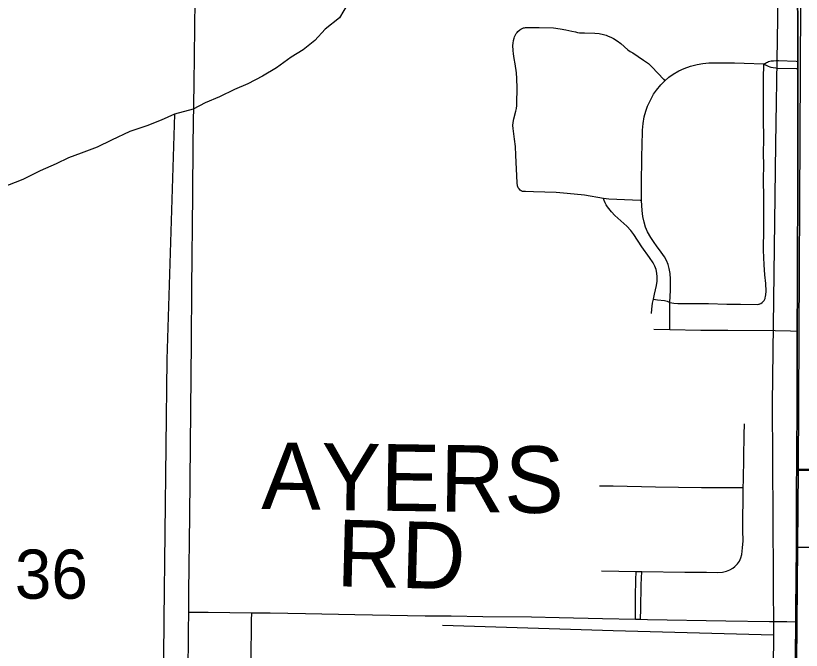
# Model space of a CAD drawing. Extents: x 0 to 34, y 0 to 22.
# Drawn here: x 7.896 to 8.565, y 18.272 to 18.813 of the extents above; entities that cross this region are included whole.
import ezdxf

# ---------------------------------------------------------------- set-up
doc = ezdxf.new("R2010")
doc.units = 0
for name, color, linetype in [('GM_X_Corporation', 7, 'Continuous'), ('GM_X_County_Road', 7, 'Continuous'), ('GM_X_Minor_River', 7, 'Continuous'), ('GM_X_Section_Text', 7, 'Continuous'), ('GM_X_Township_Road', 7, 'Continuous'), ('GM_X_Township_Road_Text', 7, 'Continuous')]:
    doc.layers.add(name, color=color, linetype=linetype)

msp = doc.modelspace()

# ---------------------------------------------------------------- linework, layer by layer
at = {"layer": 'GM_X_Corporation'}
for points in [[(8.9, 18.42344), (8.9, 19.44053), (8.56962, 19.44742), (8.56457, 18.82324), (8.56257, 18.42645)], [(7.52848, 18.83427), (8.56457, 18.82324), (8.56257, 18.42645), (8.55788, 17.86518), (7.51498, 17.8763)], [(8.9, 17.41639), (8.9, 18.42344), (8.56257, 18.42645), (8.55788, 17.86518), (8.55531, 17.77577), (8.50493, 17.42275)]]:
    msp.add_lwpolyline(points, close=True, dxfattribs=at)
for points in [[(8.56206, 18.83463), (8.56221, 18.79981), (8.56224, 18.77437), (8.56225, 18.7682), (8.56229, 18.73825), (8.56221, 18.68477), (8.56191, 18.58217), (8.56179, 18.54468), (8.56173, 18.52433), (8.56163, 18.48454), (8.56135, 18.43419), (8.56132, 18.42617), (8.56127, 18.41491), (8.56115, 18.36143), (8.56114, 18.36061), (8.56058, 18.30672), (8.56052, 18.29711), (8.56015, 18.23686)], [(8.56015, 18.23686), (8.56052, 18.29711), (8.56058, 18.30672), (8.56114, 18.36061), (8.56115, 18.36143), (8.56127, 18.41491), (8.56132, 18.42617), (8.56135, 18.43419), (8.56163, 18.48454), (8.56173, 18.52433), (8.56179, 18.54468), (8.56191, 18.58217), (8.56221, 18.68477), (8.56229, 18.73825), (8.56225, 18.7682), (8.56224, 18.77437), (8.56221, 18.79981), (8.56206, 18.83463)]]:
    msp.add_lwpolyline(points, dxfattribs=at)
at = {"layer": 'GM_X_County_Road'}
msp.add_line((8.56037, 18.2363), (8.56075, 18.29655), dxfattribs=at)
for points in [[(8.56248, 18.76765), (8.56247, 18.77381), (8.56244, 18.79925), (8.56228, 18.83407), (8.56174, 18.88072), (8.56186, 18.92237), (8.56166, 18.95472), (8.56187, 18.98456), (8.56193, 19.02064), (8.56195, 19.04425), (8.56203, 19.08291), (8.56208, 19.11277)], [(8.04319, 18.30453), (8.04338, 18.32156), (8.04407, 18.38685), (8.04485, 18.47638), (8.0455, 18.53483), (8.04584, 18.58086), (8.04665, 18.66043), (8.04704, 18.70333), (8.04789, 18.75462), (8.04863, 18.82659), (8.04849, 18.86078), (8.0482, 18.93739), (8.04843, 19.00255), (8.04869, 19.0766)], [(8.56202, 18.54413), (8.56213, 18.58161), (8.56244, 18.68421), (8.56252, 18.7377), (8.56248, 18.76765)], [(8.56154, 18.42562), (8.56157, 18.43363), (8.56186, 18.48398), (8.56196, 18.52378), (8.56202, 18.54413)], [(8.56137, 18.36006), (8.56138, 18.36088), (8.5615, 18.41435), (8.56154, 18.42562)], [(8.56075, 18.29655), (8.5608, 18.30617), (8.56137, 18.36006)], [(8.0419, 18.15097), (8.04211, 18.19851), (8.04274, 18.25005), (8.04302, 18.28863), (8.04319, 18.30453)]]:
    msp.add_lwpolyline(points, dxfattribs=at)
at = {"layer": 'GM_X_Minor_River'}
for points in [[(8.55117, 19.1356), (8.54966, 19.01986), (8.54597, 18.88176), (8.54328, 18.70341), (8.54041, 18.48254), (8.54164, 18.28513), (8.53923, 18.06955), (8.53751, 17.90633)], [(8.17916, 18.82335), (8.17182, 18.81092), (8.1596, 18.80121), (8.15079, 18.79145), (8.14086, 18.7836), (8.13058, 18.77728), (8.118, 18.76833), (8.1062, 18.76126), (8.09364, 18.75459), (8.08225, 18.7498), (8.06932, 18.74351), (8.05717, 18.73835), (8.0469, 18.73316), (8.03098, 18.72881), (8.01958, 18.72363), (8.00743, 18.71885), (7.99301, 18.7141), (7.97743, 18.7067), (7.96526, 18.70078), (7.95159, 18.69564), (7.94059, 18.6916), (7.93032, 18.68642), (7.91664, 18.68052), (7.90181, 18.67311), (7.88359, 18.66613)], [(8.03098, 18.72881), (8.02449, 18.51975), (8.022, 18.29848), (8.01975, 18.03583)], [(8.54164, 18.28513), (8.40493, 18.28875), (8.25955, 18.29323)]]:
    msp.add_lwpolyline(points, dxfattribs=at)
at = {"layer": 'GM_X_Township_Road'}
for p, q in [((8.43957, 18.54561), (8.45327, 18.54536)), ((8.3949, 18.33993), (8.4245, 18.33939))]:
    msp.add_line(p, q, dxfattribs=at)
for points in [[(8.32554, 18.66421), (8.32471, 18.66513), (8.32406, 18.66617), (8.3235, 18.66792), (8.32317, 18.67035), (8.32202, 18.69393), (8.32156, 18.70138), (8.32097, 18.70755), (8.31963, 18.71675), (8.3195, 18.71922), (8.31972, 18.72167), (8.32023, 18.72471), (8.32203, 18.7313), (8.32246, 18.73374), (8.32269, 18.7362), (8.32269, 18.73807), (8.32309, 18.75108), (8.32294, 18.75915), (8.32251, 18.76409), (8.32131, 18.77173), (8.32043, 18.77625), (8.31995, 18.78018), (8.31974, 18.78294), (8.31954, 18.78727), (8.31964, 18.78933), (8.31995, 18.7916), (8.32042, 18.79344), (8.32093, 18.79481), (8.32164, 18.79646), (8.32225, 18.79753), (8.323, 18.79847), (8.32373, 18.7992), (8.32532, 18.80057)], [(8.32532, 18.80057), (8.3263, 18.80127), (8.3274, 18.80186), (8.32844, 18.80224), (8.3293, 18.80246), (8.33022, 18.80265), (8.33176, 18.80277), (8.33379, 18.80275), (8.34186, 18.80266), (8.35413, 18.80227), (8.35981, 18.80156), (8.36467, 18.80055), (8.36956, 18.79952), (8.37276, 18.79882), (8.37457, 18.79845), (8.37623, 18.79822), (8.37818, 18.79807), (8.38059, 18.79814), (8.38928, 18.79794), (8.39299, 18.79756), (8.39663, 18.79676), (8.39882, 18.79609), (8.40073, 18.79532), (8.40306, 18.79427), (8.40523, 18.7932), (8.40843, 18.7913), (8.41137, 18.78903), (8.41739, 18.78363), (8.41937, 18.78215), (8.42154, 18.78092), (8.4309, 18.77482), (8.43489, 18.77188), (8.43768, 18.76942), (8.44325, 18.76356), (8.44778, 18.75854), (8.44892, 18.75729)], [(8.53328, 18.77157), (8.53474, 18.77229), (8.53569, 18.77277), (8.53655, 18.7732), (8.53728, 18.77357), (8.5385, 18.77386), (8.53955, 18.77411), (8.54162, 18.77427), (8.54376, 18.77443), (8.54582, 18.77451), (8.56083, 18.77388), (8.56247, 18.77381)], [(8.44892, 18.75729), (8.45242, 18.76029), (8.45606, 18.76282), (8.46099, 18.76564), (8.46557, 18.76779), (8.47093, 18.7697), (8.4764, 18.77118), (8.48138, 18.77208), (8.48641, 18.77255), (8.49393, 18.77267), (8.50827, 18.77252), (8.51652, 18.77231), (8.53328, 18.77157)], [(8.53307, 18.56963), (8.53351, 18.57024), (8.53413, 18.57129), (8.53441, 18.57185), (8.5346, 18.57247), (8.53479, 18.57351), (8.53496, 18.57498), (8.53518, 18.5782), (8.53501, 18.5845), (8.53422, 18.59196), (8.53353, 18.60058), (8.53303, 18.61299), (8.533, 18.621), (8.53331, 18.62341), (8.53333, 18.63406), (8.53323, 18.65769), (8.53305, 18.67323), (8.53328, 18.68564), (8.53317, 18.695), (8.53333, 18.70803), (8.53314, 18.72483), (8.53291, 18.74409), (8.53315, 18.75897), (8.53328, 18.77157)], [(8.53328, 18.77157), (8.53479, 18.77078), (8.53582, 18.77014), (8.53709, 18.76958), (8.53846, 18.76916), (8.53939, 18.76887), (8.54136, 18.76844), (8.54353, 18.76822), (8.54496, 18.76807), (8.56075, 18.76768), (8.56248, 18.76765)], [(8.42914, 18.65528), (8.42908, 18.66739), (8.42944, 18.69352), (8.42966, 18.70161), (8.43, 18.71533), (8.4305, 18.72097), (8.43144, 18.72657), (8.43269, 18.73147), (8.43419, 18.73565), (8.43661, 18.74079), (8.43939, 18.74573), (8.44189, 18.7494), (8.44553, 18.75376), (8.44892, 18.75729)], [(8.39658, 18.65697), (8.38043, 18.65975), (8.36561, 18.66137), (8.35632, 18.6621), (8.33707, 18.66279), (8.33012, 18.66286), (8.32888, 18.6629), (8.32756, 18.66308), (8.3266, 18.66348), (8.32554, 18.66421)], [(8.42914, 18.65528), (8.42794, 18.65532), (8.40808, 18.65605), (8.40127, 18.6564), (8.39658, 18.65697)], [(8.43927, 18.57113), (8.44019, 18.57564), (8.44183, 18.58292), (8.44237, 18.58661), (8.44251, 18.59034), (8.44221, 18.59343), (8.44154, 18.59647), (8.44047, 18.59938), (8.43901, 18.60213), (8.43594, 18.60681), (8.42934, 18.61586), (8.42258, 18.6263), (8.41988, 18.6297), (8.4165, 18.63333), (8.41144, 18.63794), (8.40636, 18.64253), (8.40342, 18.64573), (8.4001, 18.64986), (8.39896, 18.6516), (8.39805, 18.65331), (8.39718, 18.65531), (8.39658, 18.65697)], [(8.45331, 18.56843), (8.45378, 18.57897), (8.45385, 18.58825), (8.45349, 18.59312), (8.45275, 18.59731), (8.45174, 18.6008), (8.45034, 18.60414), (8.44858, 18.60732), (8.44579, 18.61132), (8.44174, 18.6168), (8.43974, 18.61954), (8.43693, 18.62387), (8.43426, 18.62849), (8.43253, 18.63258), (8.4312, 18.63682), (8.43016, 18.64177), (8.42954, 18.64679), (8.42914, 18.65528)], [(8.43751, 18.5591), (8.43776, 18.56282), (8.43857, 18.56772), (8.43927, 18.57113)], [(8.43927, 18.57113), (8.44279, 18.57078), (8.44871, 18.57018), (8.45081, 18.56964), (8.45331, 18.56843)], [(8.45327, 18.54536), (8.45328, 18.55466), (8.45329, 18.56467), (8.45331, 18.56843)], [(8.45331, 18.56843), (8.45667, 18.56789), (8.46005, 18.56756), (8.48614, 18.56742), (8.50169, 18.56713), (8.51348, 18.56689), (8.52773, 18.56684), (8.5287, 18.56688), (8.5294, 18.56698), (8.53001, 18.56722), (8.53077, 18.5676), (8.53182, 18.56833), (8.53234, 18.56886), (8.53307, 18.56963)], [(8.45327, 18.54536), (8.4795, 18.54489), (8.50258, 18.5448), (8.54308, 18.54446), (8.55614, 18.54423), (8.56202, 18.54413)], [(8.51585, 18.41081), (8.51592, 18.41714), (8.51657, 18.45575), (8.51691, 18.46508)], [(8.56137, 18.36006), (8.56138, 18.36088), (8.5615, 18.41435), (8.56154, 18.42562)], [(8.56154, 18.42562), (8.56929, 18.42559), (8.60099, 18.42549), (8.65696, 18.42547), (8.70486, 18.42549), (8.74839, 18.42531), (8.77388, 18.4253), (8.83087, 18.4253)], [(8.3932, 18.41219), (8.40501, 18.41217), (8.44107, 18.41148), (8.48023, 18.41092), (8.51007, 18.41082), (8.51585, 18.41081)], [(8.51557, 18.36546), (8.51547, 18.37418), (8.51585, 18.41081)], [(8.4245, 18.33939), (8.42922, 18.3393), (8.46595, 18.33881), (8.48456, 18.3386), (8.49382, 18.33852), (8.49805, 18.33886), (8.50155, 18.33964), (8.50431, 18.34073), (8.50686, 18.34219), (8.50871, 18.34364), (8.51077, 18.34575), (8.51245, 18.34817), (8.51374, 18.35083), (8.51459, 18.35367), (8.51525, 18.35941), (8.51557, 18.36546)], [(8.56075, 18.29655), (8.5608, 18.30617), (8.56137, 18.36006)], [(8.56137, 18.36006), (8.56968, 18.36006), (8.58217, 18.36006), (8.60468, 18.36007)], [(8.42392, 18.2987), (8.42398, 18.30725), (8.42406, 18.31833), (8.42434, 18.33187), (8.4245, 18.33939)], [(8.42826, 18.29859), (8.42844, 18.30739), (8.42886, 18.32792), (8.42922, 18.3393)], [(8.04319, 18.30453), (8.05305, 18.30462), (8.05988, 18.30468), (8.09655, 18.30419)], [(8.09655, 18.30419), (8.09648, 18.29765), (8.0961, 18.26281), (8.09616, 18.25666), (8.0966, 18.25311), (8.09704, 18.25143), (8.09841, 18.24811), (8.09964, 18.24612), (8.10157, 18.2439), (8.10385, 18.24199), (8.10638, 18.24045), (8.10912, 18.23931), (8.11201, 18.23857), (8.1156, 18.23815), (8.13421, 18.23745), (8.14909, 18.23736)], [(8.09655, 18.30419), (8.11273, 18.30398), (8.14258, 18.30341), (8.18487, 18.30264), (8.24459, 18.30143), (8.26698, 18.30144), (8.29371, 18.30086), (8.3354, 18.30064), (8.35901, 18.3001), (8.39571, 18.29934), (8.42392, 18.2987)], [(8.42392, 18.2987), (8.42826, 18.29859), (8.43426, 18.29846), (8.50082, 18.2973), (8.53815, 18.29673), (8.55306, 18.29662), (8.56075, 18.29655)]]:
    msp.add_lwpolyline(points, dxfattribs=at)

# ---------------------------------------------------------------- texts
at = {"layer": 'GM_X_Section_Text'}
msp.add_text('36', height=0.041856, rotation=0.00001, dxfattribs=at).set_placement((7.89499, 18.31612))
at = {"layer": 'GM_X_Township_Road_Text'}
for s, rotation, p in [('AYERS', 359.16627, (8.105, 18.39259)), ('RD', 358.51351, (8.16863, 18.32677))]:
    msp.add_text(s, height=0.056818, rotation=rotation, dxfattribs=at).set_placement(p)

doc.saveas('drawing.dxf')
